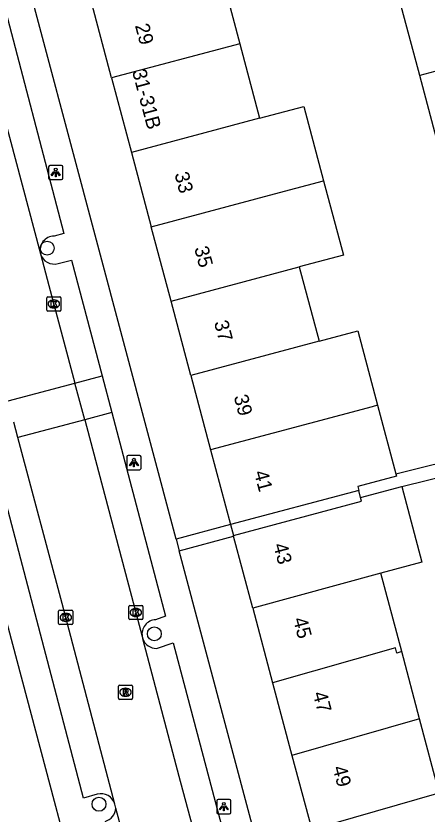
# Model space of a CAD drawing. Extents: x 162542 to 163144, y 380786 to 381511.
# Drawn here: x 162769.4 to 162798.2, y 380901.8 to 380957.7 of the extents above; entities that cross this region are included whole.
import ezdxf

# ---------------------------------------------------------------- set-up
doc = ezdxf.new("R2010")
doc.units = 0
for name, color, linetype in [('IMGEO_Boom', 7, 'Continuous'), ('IMGEO_Kolk', 7, 'Continuous'), ('IMGEO_Lichtpunt', 7, 'Continuous'), ('IMGEO_Pand', 7, 'Continuous'), ('IMGEO_Pand_nummerreeks', 7, 'Continuous'), ('IMGEO_Pand_overbouw', 7, 'Continuous'), ('IMGEO_Parkeervlak_open', 7, 'Continuous'), ('IMGEO_Rijbaan_lokaal_open', 7, 'Continuous'), ('IMGEO_Rioolput', 7, 'Continuous'), ('IMGEO_Voetpad_open', 7, 'Continuous')]:
    doc.layers.add(name, color=color, linetype=linetype)

msp = doc.modelspace()

# ---------------------------------------------------------------- linework, layer by layer
at = {"layer": 'IMGEO_Boom'}
for centre in [(162771.589, 380941.474), (162779.096, 380914.45), (162775.218, 380902.517)]:
    msp.add_circle(centre, 0.489, dxfattribs=at)
at = {"layer": 'IMGEO_Kolk'}
for p, q in [((162771.554, 380937.136), (162771.554, 380937.988)), ((162771.629, 380938.062), (162772.481, 380938.062)), ((162772.042, 380937.842), (162772.067, 380937.842)), ((162772.555, 380937.988), (162772.555, 380937.136)), ((162772.065, 380937.282), (162772.04, 380937.282)), ((162772.481, 380937.062), (162771.629, 380937.062)), ((162772.392, 380915.179), (162772.392, 380916.031)), ((162772.467, 380916.105), (162773.319, 380916.105)), ((162773.393, 380916.031), (162773.393, 380915.179)), ((162777.301, 380915.522), (162777.301, 380916.374)), ((162777.376, 380916.448), (162778.228, 380916.448)), ((162777.789, 380916.228), (162777.814, 380916.228)), ((162778.302, 380916.374), (162778.302, 380915.522)), ((162772.88, 380915.885), (162772.905, 380915.885)), ((162778.228, 380915.448), (162777.376, 380915.448)), ((162777.812, 380915.668), (162777.787, 380915.668)), ((162773.319, 380915.105), (162772.467, 380915.105)), ((162772.903, 380915.325), (162772.878, 380915.325))]:
    msp.add_line(p, q, dxfattribs=at)
for points in [[(162771.554, 380937.136), (162771.554, 380937.988)], [(162771.629, 380938.062), (162772.481, 380938.062)], [(162771.875, 380937.762), (162771.998, 380937.762), (162771.998, 380937.611), (162772.128, 380937.762), (162772.292, 380937.762), (162772.146, 380937.611), (162772.299, 380937.362), (162772.147, 380937.362), (162772.062, 380937.526), (162771.998, 380937.459), (162771.998, 380937.362), (162771.875, 380937.362), (162771.875, 380937.762)], [(162772.555, 380937.988), (162772.555, 380937.136)], [(162772.481, 380937.062), (162771.629, 380937.062)], [(162772.392, 380915.179), (162772.392, 380916.031)], [(162772.467, 380916.105), (162773.319, 380916.105)], [(162773.393, 380916.031), (162773.393, 380915.179)], [(162777.301, 380915.522), (162777.301, 380916.374)], [(162777.376, 380916.448), (162778.228, 380916.448)], [(162777.622, 380916.148), (162777.745, 380916.148), (162777.745, 380915.997), (162777.875, 380916.148), (162778.039, 380916.148), (162777.893, 380915.997), (162778.046, 380915.748), (162777.894, 380915.748), (162777.809, 380915.912), (162777.745, 380915.845), (162777.745, 380915.748), (162777.622, 380915.748), (162777.622, 380916.148)], [(162778.302, 380916.374), (162778.302, 380915.522)], [(162772.713, 380915.805), (162772.836, 380915.805), (162772.836, 380915.654), (162772.966, 380915.805), (162773.13, 380915.805), (162772.984, 380915.654), (162773.137, 380915.405), (162772.985, 380915.405), (162772.9, 380915.569), (162772.836, 380915.502), (162772.836, 380915.405), (162772.713, 380915.405), (162772.713, 380915.805)], [(162778.228, 380915.448), (162777.376, 380915.448)], [(162773.319, 380915.105), (162772.467, 380915.105)]]:
    msp.add_lwpolyline(points, dxfattribs=at)
for centre, start, end in [((162771.631, 380937.986), 91.552, 178.448), ((162771.631, 380937.986), 91.552, 178.448), ((162772.479, 380937.986), 1.552, 88.448), ((162772.479, 380937.986), 1.552, 88.448), ((162771.631, 380937.138), 181.552, 268.448), ((162771.631, 380937.138), 181.552, 268.448), ((162772.479, 380937.138), 271.552, 358.448), ((162772.479, 380937.138), 271.552, 358.448), ((162772.469, 380916.029), 91.552, 178.448), ((162772.469, 380916.029), 91.552, 178.448), ((162773.317, 380916.029), 1.552, 88.448), ((162773.317, 380916.029), 1.552, 88.448), ((162777.378, 380916.372), 91.552, 178.448), ((162777.378, 380916.372), 91.552, 178.448), ((162778.226, 380916.372), 1.552, 88.448), ((162778.226, 380916.372), 1.552, 88.448), ((162777.378, 380915.524), 181.552, 268.448), ((162777.378, 380915.524), 181.552, 268.448), ((162778.226, 380915.524), 271.552, 358.448), ((162778.226, 380915.524), 271.552, 358.448), ((162772.469, 380915.181), 181.552, 268.448), ((162772.469, 380915.181), 181.552, 268.448), ((162773.317, 380915.181), 271.552, 358.448), ((162773.317, 380915.181), 271.552, 358.448)]:
    msp.add_arc(centre, 0.0765, start, end, dxfattribs=at)
for centre, major_axis, ratio, start_param, end_param in [((162772.041, 380937.562), (-0.387, 0.002), 0.722429, 4.712389, 7.853982), ((162772.066, 380937.562), (-0.39, 0.002), 0.717154, 1.570796, 4.712389), ((162777.788, 380915.948), (-0.387, 0.002), 0.722429, 4.712389, 7.853982), ((162777.813, 380915.948), (-0.39, 0.002), 0.717154, 1.570796, 4.712389), ((162772.879, 380915.605), (-0.387, 0.002), 0.722429, 4.712389, 7.853982), ((162772.904, 380915.605), (-0.39, 0.002), 0.717154, 1.570796, 4.712389)]:
    msp.add_ellipse(centre, major_axis=major_axis, ratio=ratio, start_param=start_param, end_param=end_param, dxfattribs=at)
at = {"layer": 'IMGEO_Lichtpunt'}
for p, q in [((162772.591, 380947.268), (162771.783, 380947.268)), ((162772.591, 380947.268), (162771.783, 380947.268)), ((162771.689, 380947.173), (162771.689, 380946.366)), ((162771.689, 380947.173), (162771.689, 380946.366)), ((162772.685, 380946.366), (162772.685, 380947.173)), ((162772.685, 380946.366), (162772.685, 380947.173)), ((162771.783, 380946.272), (162772.591, 380946.272)), ((162771.783, 380946.272), (162772.591, 380946.272)), ((162777.168, 380926.854), (162777.168, 380926.047)), ((162777.168, 380926.854), (162777.168, 380926.047)), ((162778.07, 380926.949), (162777.262, 380926.949)), ((162778.07, 380926.949), (162777.262, 380926.949)), ((162778.164, 380926.047), (162778.164, 380926.854)), ((162778.164, 380926.047), (162778.164, 380926.854)), ((162777.262, 380925.953), (162778.07, 380925.953)), ((162777.262, 380925.953), (162778.07, 380925.953)), ((162783.47, 380902.75), (162783.47, 380901.943)), ((162783.47, 380902.75), (162783.47, 380901.943)), ((162784.372, 380902.845), (162783.564, 380902.845)), ((162784.372, 380902.845), (162783.564, 380902.845)), ((162784.466, 380901.943), (162784.466, 380902.75)), ((162784.466, 380901.943), (162784.466, 380902.75)), ((162783.564, 380901.849), (162784.372, 380901.849)), ((162783.564, 380901.849), (162784.372, 380901.849))]:
    msp.add_line(p, q, dxfattribs=at)
for points in [[(162772.063, 380946.837), (162772.102, 380946.809), (162771.914, 380946.547), (162771.876, 380946.574), (162772.063, 380946.837)], [(162772.165, 380946.789), (162772.212, 380946.789), (162772.212, 380946.467), (162772.165, 380946.467), (162772.165, 380946.789)], [(162772.275, 380946.809), (162772.313, 380946.836), (162772.5, 380946.574), (162772.461, 380946.546), (162772.275, 380946.809)], [(162777.542, 380926.518), (162777.581, 380926.49), (162777.393, 380926.228), (162777.355, 380926.255), (162777.542, 380926.518)], [(162777.644, 380926.47), (162777.691, 380926.47), (162777.691, 380926.148), (162777.644, 380926.148), (162777.644, 380926.47)], [(162777.754, 380926.49), (162777.792, 380926.517), (162777.979, 380926.255), (162777.94, 380926.227), (162777.754, 380926.49)], [(162783.844, 380902.414), (162783.883, 380902.386), (162783.695, 380902.124), (162783.657, 380902.151), (162783.844, 380902.414)], [(162783.946, 380902.366), (162783.993, 380902.366), (162783.993, 380902.044), (162783.946, 380902.044), (162783.946, 380902.366)], [(162784.056, 380902.386), (162784.094, 380902.413), (162784.281, 380902.151), (162784.242, 380902.123), (162784.056, 380902.386)]]:
    msp.add_lwpolyline(points, dxfattribs=at)
for centre in [(162772.188, 380946.971), (162777.667, 380926.652), (162783.969, 380902.548)]:
    msp.add_circle(centre, 0.0994, dxfattribs=at)
for centre, start, end in [((162771.783, 380947.173), 90, 180), ((162771.783, 380947.173), 90, 180), ((162772.591, 380947.173), 0, 90), ((162772.591, 380947.173), 0, 90), ((162771.783, 380946.366), 180, 270), ((162771.783, 380946.366), 180, 270), ((162772.591, 380946.366), 270, 0), ((162772.591, 380946.366), 270, 360), ((162777.262, 380926.854), 90, 180), ((162777.262, 380926.854), 90, 180), ((162778.07, 380926.854), 0, 90), ((162778.07, 380926.854), 0, 90), ((162777.262, 380926.047), 180, 270), ((162777.262, 380926.047), 180, 270), ((162778.07, 380926.047), 270, 0), ((162778.07, 380926.047), 270, 360), ((162783.564, 380902.75), 90, 180), ((162783.564, 380902.75), 90, 180), ((162784.372, 380902.75), 0, 90), ((162784.372, 380902.75), 0, 90), ((162783.564, 380901.943), 180, 270), ((162783.564, 380901.943), 180, 270), ((162784.372, 380901.943), 270, 0), ((162784.372, 380901.943), 270, 360)]:
    msp.add_arc(centre, 0.0946, start, end, dxfattribs=at)
at = {"layer": 'IMGEO_Pand'}
for points in [[(162783.702, 380960.994), (162785.089, 380955.785)], [(162776.104, 380953.39), (162774.717, 380958.599)], [(162797.692, 380953.565), (162796.291, 380958.771)], [(162785.089, 380955.785), (162776.104, 380953.39)], [(162785.089, 380955.785), (162786.477, 380950.576)], [(162799.794, 380954.126), (162797.692, 380953.565)], [(162799.092, 380948.361), (162797.692, 380953.565)], [(162776.104, 380953.39), (162777.492, 380948.181)], [(162786.477, 380950.576), (162789.569, 380951.4), (162790.956, 380946.192)], [(162786.477, 380950.576), (162777.492, 380948.181)], [(162777.492, 380948.181), (162778.879, 380942.973)], [(162778.879, 380942.973), (162787.864, 380945.368), (162790.956, 380946.192)], [(162790.956, 380946.192), (162792.343, 380940.984), (162789.251, 380940.16)], [(162780.266, 380937.765), (162778.879, 380942.973)], [(162780.266, 380937.765), (162789.251, 380940.16)], [(162789.251, 380940.16), (162790.638, 380934.951)], [(162781.653, 380932.556), (162780.266, 380937.765)], [(162790.638, 380934.951), (162793.348, 380935.673), (162794.735, 380930.466)], [(162790.638, 380934.951), (162781.653, 380932.556)], [(162781.653, 380932.556), (162783.04, 380927.349)], [(162794.735, 380930.466), (162794.354, 380930.365), (162783.04, 380927.349)], [(162794.735, 380930.466), (162796.013, 380925.666)], [(162783.04, 380927.349), (162784.437, 380922.105)], [(162796.013, 380925.666), (162796.06, 380925.49), (162793.35, 380924.768), (162793.422, 380924.5), (162784.437, 380922.105)], [(162784.652, 380921.296), (162784.64, 380921.342), (162793.626, 380923.737), (162793.556, 380923.998), (162796.44, 380924.766)], [(162796.44, 380924.766), (162797.847, 380919.483), (162794.967, 380918.7)], [(162785.994, 380916.261), (162784.652, 380921.296)], [(162794.967, 380918.7), (162785.994, 380916.261)], [(162796.43, 380913.206), (162794.967, 380918.7)], [(162785.994, 380916.261), (162787.389, 380911.023)], [(162796.43, 380913.206), (162796.096, 380913.108), (162795.997, 380913.48), (162787.389, 380911.023)], [(162797.685, 380908.496), (162796.43, 380913.206)], [(162787.389, 380911.023), (162788.743, 380905.938)], [(162797.685, 380908.496), (162788.743, 380905.938)], [(162799.067, 380903.307), (162797.685, 380908.496)], [(162788.743, 380905.938), (162790.126, 380900.745)], [(162790.126, 380900.745), (162799.067, 380903.307)]]:
    msp.add_lwpolyline(points, dxfattribs=at)
at = {"layer": 'IMGEO_Pand_overbouw'}
msp.add_lwpolyline([(162793.626, 380923.737), (162793.556, 380923.998), (162793.422, 380924.5), (162784.437, 380922.105), (162784.64, 380921.342)], close=True, dxfattribs=at)
at = {"layer": 'IMGEO_Parkeervlak_open'}
for points in [[(162773.532, 380932.015), (162775.443, 380932.523)], [(162776.12, 380929.96), (162774.215, 380929.454)]]:
    msp.add_lwpolyline(points, dxfattribs=at)
at = {"layer": 'IMGEO_Rijbaan_lokaal_open'}
for points in [[(162766.115, 380959.838), (162767.646, 380954.085), (162771.115, 380941.082)], [(162771.115, 380941.082), (162771.712, 380938.843), (162773.532, 380932.015)], [(162768.845, 380930.769), (162773.532, 380932.015)], [(162774.215, 380929.454), (162773.532, 380932.015)], [(162774.215, 380929.454), (162769.53, 380928.208)], [(162774.215, 380929.454), (162778.249, 380914.26)], [(162769.53, 380928.208), (162769.244, 380929.276)], [(162776.334, 380902.519), (162772.635, 380916.59), (162769.53, 380928.208)], [(162778.249, 380914.26), (162778.29, 380914.105)], [(162784.888, 380889.476), (162784.223, 380891.867), (162780.844, 380904.471), (162778.29, 380914.105)], [(162776.409, 380902.238), (162776.334, 380902.519)], [(162780.272, 380887.798), (162776.409, 380902.238)]]:
    msp.add_lwpolyline(points, dxfattribs=at)
at = {"layer": 'IMGEO_Rioolput'}
for p, q in [((162776.576, 380909.936), (162776.576, 380910.788)), ((162776.651, 380910.862), (162777.503, 380910.862)), ((162777.064, 380910.642), (162777.089, 380910.642)), ((162777.577, 380910.788), (162777.577, 380909.936)), ((162777.503, 380909.862), (162776.651, 380909.862)), ((162777.087, 380910.082), (162777.062, 380910.082))]:
    msp.add_line(p, q, dxfattribs=at)
for points in [[(162776.576, 380909.936), (162776.576, 380910.788)], [(162776.651, 380910.862), (162777.503, 380910.862)], [(162777.165, 380910.56), (162776.913, 380910.562), (162776.913, 380910.162)], [(162777.091, 380910.481), (162777.037, 380910.481), (162777.037, 380910.4)], [(162777.037, 380910.4), (162777.089, 380910.4)], [(162777.577, 380910.788), (162777.577, 380909.936)], [(162777.503, 380909.862), (162776.651, 380909.862)], [(162776.913, 380910.162), (162777.037, 380910.162), (162777.037, 380910.324), (162777.048, 380910.324)], [(162777.095, 380910.295), (162777.166, 380910.162), (162777.306, 380910.162), (162777.241, 380910.288)]]:
    msp.add_lwpolyline(points, dxfattribs=at)
for centre, radius, start, end in [((162776.653, 380910.786), 0.0765, 91.552, 178.448), ((162776.653, 380910.786), 0.0765, 91.552, 178.448), ((162777.073, 380910.589), 0.19, 274.7715, 282.9687), ((162777.097, 380910.385), 0.0964, 77.0061, 93.1865), ((162777.111, 380910.442), 0.0378, 276.6634, 79.6772), ((162777.164, 380910.45), 0.109, 350.3612, 89.416), ((162777.162, 380910.45), 0.112, 277.5842, 350.9817), ((162777.501, 380910.786), 0.0765, 1.552, 88.448), ((162777.501, 380910.786), 0.0765, 1.552, 88.448), ((162776.653, 380909.938), 0.0765, 181.552, 268.448), ((162776.653, 380909.938), 0.0765, 181.552, 268.448), ((162777.047, 380910.271), 0.0533, 26.0293, 88.6989), ((162777.146, 380910.235), 0.108, 29.5134, 73.7905), ((162777.501, 380909.938), 0.0765, 271.552, 358.448), ((162777.501, 380909.938), 0.0765, 271.552, 358.448)]:
    msp.add_arc(centre, radius, start, end, dxfattribs=at)
for centre, major_axis, ratio, start_param, end_param in [((162777.063, 380910.362), (-0.387, 0.002), 0.722429, 4.712389, 7.853982), ((162777.088, 380910.362), (-0.39, 0.002), 0.717154, 1.570796, 4.712389)]:
    msp.add_ellipse(centre, major_axis=major_axis, ratio=ratio, start_param=start_param, end_param=end_param, dxfattribs=at)
at = {"layer": 'IMGEO_Voetpad_open'}
for points in [[(162780.617, 380921.086), (162763.955, 380983.585)], [(162767.263, 380959.225), (162768.266, 380959.557), (162772.766, 380942.488), (162772.068, 380942.321)], [(162772.351, 380940.392), (162773.303, 380940.622), (162775.443, 380932.523)], [(162775.443, 380932.523), (162776.12, 380929.96)], [(162776.12, 380929.96), (162779.888, 380915.697), (162779.19, 380915.442)], [(162796.013, 380925.666), (162806.622, 380928.295), (162806.122, 380930.314)], [(162775.099, 380903.218), (162774.135, 380902.949), (162767.576, 380927.887), (162768.553, 380928.156)], [(162796.44, 380924.766), (162806.857, 380927.348), (162807.283, 380925.632)], [(162784.437, 380922.105), (162780.617, 380921.086)], [(162780.617, 380921.086), (162780.832, 380920.278)], [(162780.832, 380920.278), (162784.652, 380921.296)], [(162790.444, 380878.831), (162787.726, 380889.027), (162787.979, 380889.585), (162788.858, 380889.82), (162787.754, 380894.316), (162780.832, 380920.278)], [(162768.14, 380917.522), (162776.41, 380886.464), (162777.36, 380886.698), (162778.067, 380886.244), (162780.774, 380876.082)], [(162779.257, 380913.435), (162780.412, 380913.819), (162786.011, 380892.739)]]:
    msp.add_lwpolyline(points, dxfattribs=at)
for centre, radius, start, end in [((162772.09, 380941.318), 1.003, 91.2489, 193.6184), ((162772.085, 380941.368), 1.012, 196.4377, 285.2172), ((162779.235, 380914.44), 1.003, 92.5912, 190.3616), ((162779.235, 380914.437), 1.002, 199.3325, 271.2341), ((162775.359, 380902.236), 1.015, 16.1591, 104.8218), ((162775.355, 380902.33), 1.058, 286.1229, 355.0017)]:
    msp.add_arc(centre, radius, start, end, dxfattribs=at)

# ---------------------------------------------------------------- texts
at = {"layer": 'IMGEO_Pand_nummerreeks'}
for s, rotation, p in [('29', 284.9143, (162777.733, 380957.067)), ('31-31B', 284.9196, (162777.528, 380953.87)), ('33', 284.9139, (162780.501, 380946.67)), ('35', 284.9143, (162781.887, 380941.471)), ('37', 284.9143, (162783.271, 380936.273)), ('39', 284.9139, (162784.655, 380931.074)), ('41', 284.9139, (162786.07, 380925.767)), ('43', 284.9139, (162787.424, 380920.677)), ('45', 284.9143, (162788.81, 380915.478)), ('47', 284.9143, (162790.194, 380910.28)), ('49', 284.9143, (162791.579, 380905.081))]:
    msp.add_text(s, height=1, rotation=rotation, dxfattribs=at).set_placement(p)

doc.saveas('drawing.dxf')
